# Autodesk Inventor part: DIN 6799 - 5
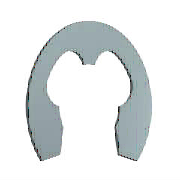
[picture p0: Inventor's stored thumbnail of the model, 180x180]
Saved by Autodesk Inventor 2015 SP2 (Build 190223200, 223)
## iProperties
Created: 2012-02
Part Number: DIN 6799 - 5
Material: Stahl, weich
Description: Sicherungsscheibe
Document SubType Name: Modeling
Standard: DIN 6799
Designer: rYan
Standards Organization: DIN
Language: de-DE
Size Designation: 5
Categories: <MemberInstance><Categories><Category DisplayName="Wellenteile" InternalName="7f7aeb1f-a693-4053-b835-cee3144e0d98" Mnemonic="SHFT"><Category DisplayName="Siche
Density: 7.85 g/cm^3
Mass: 0.268642 g
Surface Area: 1.34121 cm^2
Volume: 0.0342219 cm^3
Appearance: Halbpoliert
IsCustomPart: 0
Author: rYan
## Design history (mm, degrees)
sketch "Skizze1"
  geometry: L1 (-0.5, 0.024)-(0, 0.024) reference; L2 (-7.91, 0)-(7.91, 0) reference; L3 (-2.291, -3.976)-(2.291, -3.976); L4 (0, 4.592)-(0, -8.836) reference; L5 (-3, -1.976)-(-2.51, -1.976); L6 (-0.5, 0.024)-(-0.5, 0.509); L7 (0, 2.674)-(2.53, 2.674); L8 (-2.291, -3.976)-(-3.095, -6.309); L9 (0, -0.476)-(-1.278, -0.476); L10 (2.291, -3.976)-(3.095, -6.309); L11 (3, -1.976)-(2.51, -1.976); L12 (0.5, 0.024)-(0.5, 0.509); C1 r 3 at (0, -2.976); A1 r 2.5 centre (0, -2.976) between (-2.368, -2.174) and (-2.291, -3.976); A2 r 0.5 centre (0, 0.024) between (-0.5, 0.024) and (0.5, 0.024); A3 r 5.65 centre (0, -2.976) between (4.386, -6.538) and (-4.386, -6.538); A4 r 4 centre (0, -2.976) between (-1, 0.897) and (-3.529, -1.094); A5 r 0.4 centre (-0.9, 0.509) between (-0.5, 0.509) and (-1, 0.897); A6 r 0.6 centre (-3, -1.376) between (-3.529, -1.094) and (-3, -1.976); A7 r 0.15 centre (-2.51, -2.126) between (-2.368, -2.174) and (-2.51, -1.976); A8 r 0.75 centre (-3.804, -6.065) between (-4.386, -6.538) and (-3.095, -6.309); A9 r 0.75 centre (3.804, -6.065) between (3.095, -6.309) and (4.386, -6.538); A10 r 2.5 centre (0, -2.976) between (2.291, -3.976) and (2.368, -2.174); A11 r 0.15 centre (2.51, -2.126) between (2.51, -1.976) and (2.368, -2.174); A12 r 0.6 centre (3, -1.376) between (3, -1.976) and (3.529, -1.094); A13 r 4 centre (0, -2.976) between (3.529, -1.094) and (1, 0.897); A14 r 0.4 centre (0.9, 0.509) between (1, 0.897) and (0.5, 0.509); 1 further point
  constraints: 30 point on circle, 20 end point, 15 centre point, 13 symmetric about line, 12 tangent, 8 point on line, 4 parallel, 2 coincident, 2 horizontal, 1 concentric, 1 perpendicular, 1 vertical alignment, 9 other
  dimensions: "d0" = 6 diameter of C1 (= WD); "d3" = 1 distance from line of A1.centre L3 (= 0.2 x ND); "d4" = 0.5 radius of A2 (= 0.1 x ND); "d5" = 11.3 diameter of A3 (= SD2); "d8" = 4 radius of A4 (= 0.8 x ND); "d9" = 1 distance from line of A1.centre L5 (= 0.2 x ND); "d10" = 0.4 radius of A5 (= 0.08 x ND); "d11" = 0.6 radius of A6 (= 0.12 x ND); "d12" = 0.15 radius of A7 (= 0.03 x ND); "d13" = 0.75 radius of A8 (= 0.15 x ND); "d14" = 2.5 distance from line of A1.centre L9 (= 0.5 x ND); "d15" = 2.5 radius of A1 (= 0.5 x ND)
extrude "Körper" new body sketch "Skizze1" distance "d16" = 0.7 (= SD); taper "d17" = 0 deg
workaxis "Work Axis1"
workaxis "Work Axis2"
workplane "Work Plane1"
body "Solid1"
other parameters: "ND" = 5 [user parameter; used in 14 equation terms], "SD" = 0.7 [user parameter; used in 1 equation term], "WD" = 6 [user parameter; used in 1 equation term], "d1" = 8 (= 1.6 x ND), "d2" = 5 (= ND), "SD2" = 11.3 [user parameter; used in 1 equation term], "d6" = 5 (= ND), "d7" = 0.75 (= 0.15 x ND), "d18" = 0, "d19" = 0, "d27" = 0, "d28" = 0, "WDMIN" = 5 [user parameter], "SNB" = 0.74 [user parameter], "WDMAX" = 7 [user parameter], "BUBRMI" = 1.2 [user parameter]
